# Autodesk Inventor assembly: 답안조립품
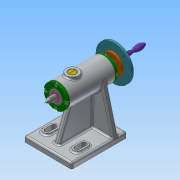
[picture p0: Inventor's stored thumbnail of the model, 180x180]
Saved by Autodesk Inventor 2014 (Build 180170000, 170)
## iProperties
Created: 2019-10
Part Number: 답안조립품
Document SubType Name: Assembly
Designer: NET
Author: NET
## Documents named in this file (18)
- C:\Users\NET\Desktop\491004V1030\답안조립품.iam
- C:\Users\NET\Desktop\491004V1030\본체.ipt
- C:\Users\NET\Desktop\491004V1030\부시.ipt
- C:\Users\NET\Desktop\491004V1030\커버.ipt
- C:\Users\NET\Desktop\491004V1030\볼트 M3.ipt
- C:\Users\NET\Desktop\491004V1030\나사축.ipt
- C:\Users\NET\Desktop\491004V1030\키 4 x 4 x 10.ipt
- C:\Users\NET\Desktop\491004V1030\돌림판.ipt
- C:\Users\NET\Desktop\491004V1030\플랜지.ipt
- C:\Users\NET\Desktop\491004V1030\와셔.ipt
- C:\Users\NET\Desktop\491004V1030\너트 M8.ipt
- C:\Users\NET\Desktop\491004V1030\핸들.ipt
- C:\Users\NET\Desktop\491004V1030\슬리브.ipt
- C:\Users\NET\Desktop\491004V1030\중공축.ipt
- C:\Users\NET\Desktop\491004V1030\나사.ipt
- C:\Users\NET\Desktop\491004V1030\센터홀더.ipt
- C:\Users\NET\Desktop\491004V1030\멈춤나사 M3.ipt
- C:\Users\NET\Desktop\491004V1030\센터.ipt
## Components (2 placed, 2 different names)
1. 플랜지:1
2. 핸들:1
